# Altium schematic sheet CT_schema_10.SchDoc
size 391 x 238 mm
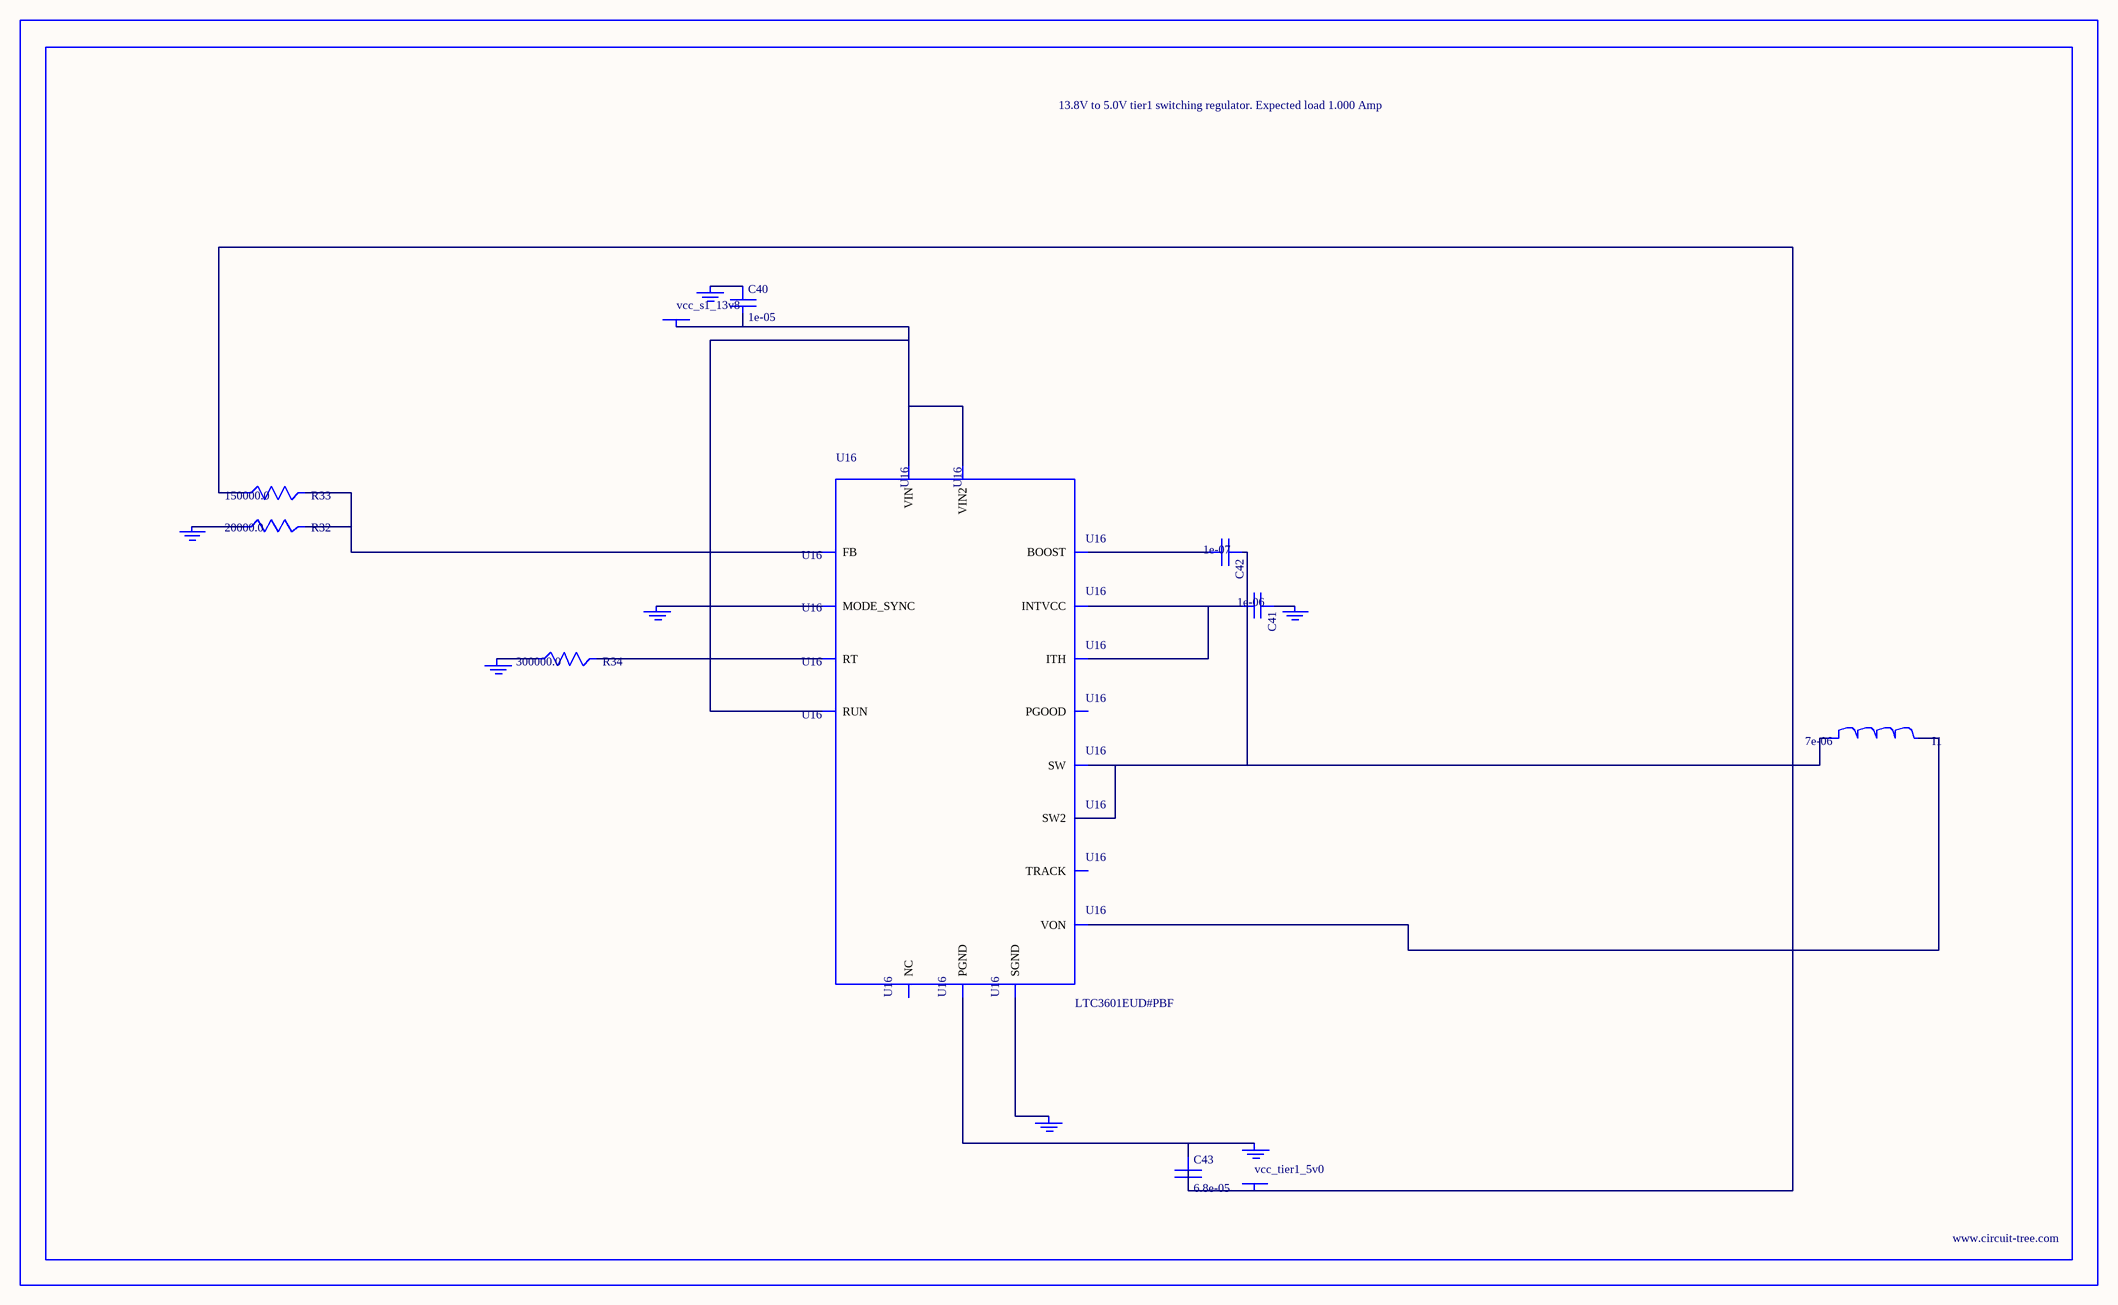
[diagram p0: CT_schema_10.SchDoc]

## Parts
BORDER9  (no value)
C40  1e-05  [C0805]
C41  1e-06  [C0603]
C42  1e-07  [C0402]
C43  6.8e-05  [2220]
GND_INSTANCE_9_0  (no value)
GND_INSTANCE_9_1  (no value)
GND_INSTANCE_9_2  (no value)
GND_INSTANCE_9_3  (no value)
GND_INSTANCE_9_4  (no value)
GND_INSTANCE_9_5  (no value)
GND_INSTANCE_9_6  (no value)
I1  7e-06  [DR1040]
POWER_INSTANCE_9_0  vcc_s1_13v8
POWER_INSTANCE_9_1  vcc_tier1_5v0
R32  20000.0  [R0603]
R33  150000.0  [R0603]
R34  300000.0  [R0603]
U16  LTC3601EUD#PBF  [QFN-16_EP]

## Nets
NetC40_1: C40.1 GND_INSTANCE_9_5.0(GND)
NetC40_2: C40.2 POWER_INSTANCE_9_0.0(PWR) U16.14(RUN) U16.15(VIN) U16.16(VIN2)
NetC41_1: C41.1 GND_INSTANCE_9_1.0(GND)
NetC41_2: C41.2 U16.7(INTVCC) U16.12(ITH)
NetC42_1: C42.1 I1.1 U16.3(SW) U16.4(SW2)
NetC42_2: C42.2 U16.6(BOOST)
NetC43_1: C43.1 GND_INSTANCE_9_6.0(GND) U16.17(PGND)
NetC43_2: C43.2 I1.2 POWER_INSTANCE_9_1.0(PWR) R33.1 U16.8(VON)
NetGND_INSTANCE_9_0_0: GND_INSTANCE_9_0.0(GND) U16.1(MODE_SYNC)
NetGND_INSTANCE_9_2_0: GND_INSTANCE_9_2.0(GND) U16.9(SGND)
NetGND_INSTANCE_9_3_0: GND_INSTANCE_9_3.0(GND) R34.1
NetGND_INSTANCE_9_4_0: GND_INSTANCE_9_4.0(GND) R32.1
NetR32_2: R32.2 R33.2 U16.11(FB)
NetR34_2: R34.2 U16.10(RT)

Not connected (* = marked no-connect by the designer): U16 2(PGOOD) 5(NC) 13(TRACK)

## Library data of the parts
BORDER9 = BORDER_PAGE9
C40 = C0805C106K8RACTU
C41 = C0603C105K3RACTU
C42 = C0402C104K3RACTU
C43 = C5750X5R1A686M
GND_INSTANCE_9_0-GND_INSTANCE_9_6 = GND
I1 = DR1040-7R0-R
POWER_INSTANCE_9_0 POWER_INSTANCE_9_1 = PWR
R32 = RC0603JR-0720KL
R33 = RC0603JR-07150KL
R34 = RC0603JR-07300KL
